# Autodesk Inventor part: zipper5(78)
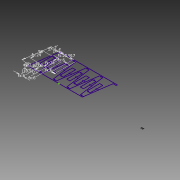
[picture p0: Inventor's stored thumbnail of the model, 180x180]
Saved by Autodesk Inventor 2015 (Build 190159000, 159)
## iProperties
Created: 2015-02
Part Number: zipper5(78)
Material: Generic
Document SubType Name: Modeling
Designer: sungeun
Density: 1 g/cm^3
Appearance: Default
Author: sungeun
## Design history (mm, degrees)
sketch "Sketch1"
  geometry: L1 (0, 2)-(6.959, 51.513); L2 (6.959, 51.513)-(12.959, 51.513); L3 (12.959, 51.513)-(19.917, 2); L4 (19.917, 2)-(25.917, 2); L5 (25.917, 0)-(0, 0); L6 (6.959, 53.513)-(38.876, 53.513); L7 (38.876, 51.513)-(32.876, 51.513); L8 (32.876, 51.513)-(25.917, 2); L9 (6.959, 53.513)-(6.959, 51.513); L10 (0, 2)-(0, 0); L11 (210.186, 7.284)-(215.439, 7.284); L12 (215.439, 7.284)-(215.439, 3.639); L13 (215.439, 3.639)-(210.186, 3.639); L14 (210.186, 3.639)-(210.186, 7.284); L15 (6.959, 38.757)-(12.959, 38.757); L16 (12.959, 38.757)-(12.959, 14.757); L17 (12.959, 14.757)-(6.959, 14.757); L18 (6.959, 14.757)-(6.959, 38.757); L19 (19.917, 38.757)-(25.917, 38.757); L20 (25.917, 38.757)-(25.917, 14.757); L21 (25.917, 14.757)-(19.917, 14.757); L22 (19.917, 14.757)-(19.917, 38.757); L23 (32.876, 53.513)-(64.793, 53.513); L24 (32.876, 51.513)-(38.876, 51.513); L25 (25.917, 2)-(32.876, 51.513); L26 (38.876, 51.513)-(45.835, 2); L27 (32.876, 38.757)-(38.876, 38.757); L28 (38.876, 38.757)-(38.876, 14.757); L29 (32.876, 14.757)-(32.876, 38.757); L30 (38.876, 14.757)-(32.876, 14.757); L31 (51.835, 0)-(25.917, 0); L32 (45.835, 2)-(51.835, 2); L33 (51.835, 14.757)-(45.835, 14.757); L34 (51.835, 38.757)-(51.835, 14.757); L35 (45.835, 14.757)-(45.835, 38.757); L36 (45.835, 38.757)-(51.835, 38.757); L37 (58.793, 51.513)-(51.835, 2); L38 (64.793, 51.513)-(58.793, 51.513); L39 (58.793, 53.513)-(90.711, 53.513); L40 (58.793, 51.513)-(64.793, 51.513); L41 (51.835, 2)-(58.793, 51.513); L42 (64.793, 51.513)-(71.752, 2); L43 (58.793, 38.757)-(64.793, 38.757); L44 (64.793, 38.757)-(64.793, 14.757); L45 (58.793, 14.757)-(58.793, 38.757); L46 (64.793, 14.757)-(58.793, 14.757); L47 (77.752, 0)-(51.835, 0); L48 (71.752, 2)-(77.752, 2); L49 (77.752, 14.757)-(71.752, 14.757); L50 (77.752, 38.757)-(77.752, 14.757); L51 (71.752, 14.757)-(71.752, 38.757); L52 (71.752, 38.757)-(77.752, 38.757); L53 (84.711, 51.513)-(77.752, 2); L54 (90.711, 51.513)-(84.711, 51.513); L55 (84.711, 53.513)-(116.628, 53.513); L56 (84.711, 51.513)-(90.711, 51.513); L57 (77.752, 2)-(84.711, 51.513); L58 (90.711, 51.513)-(97.669, 2); L59 (84.711, 38.757)-(90.711, 38.757); L60 (90.711, 38.757)-(90.711, 14.757); L61 (84.711, 14.757)-(84.711, 38.757); L62 (90.711, 14.757)-(84.711, 14.757); L63 (103.669, 0)-(77.752, 0); L64 (97.669, 2)-(103.669, 2)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; 34 further points
  constraints: 136 end point, 9 midpoint, 7 parallel, 4 horizontal, 4 horizontal alignment, 3 perpendicular, 2 equal length, 2 vertical alignment, 1 collinear, 1 vertical, 130 other
  dimensions: "d0" = 2 distance of L5.end L1.start; "d1" = 6 distance of L1.end L2.end; "d2" = 82 deg angle of L5 L1; "d4" = 2 distance between parallel lines of L5 L4 (= d0); "d14" = 2 distance of L1.end L6.start (= d4); "d17" = 2 distance between parallel lines of L6 L7 (= d0); "d18" = 6 distance of L7.start L7.end (= d1); "d34" = 6 distance of L3.end L4.end (= d1); "d35" = 19.91731 distance of L1.start L3.end (derived); "d36" = 50 distance of L1.start L1.end; "d44" = 6 distance of L16.end L17.end (= d1); "d45" = 24 distance of L17.end L15.start (= 4 x d1); "d46" = 6 distance of L20.end L21.end (= d1); "d47" = 24 distance of L21.end L19.start (= d45); "d50" = 25.91731 distance of L6.start L23.start (= d35 + d1)
other parameters: "d6" = 56.39702 (derived)
